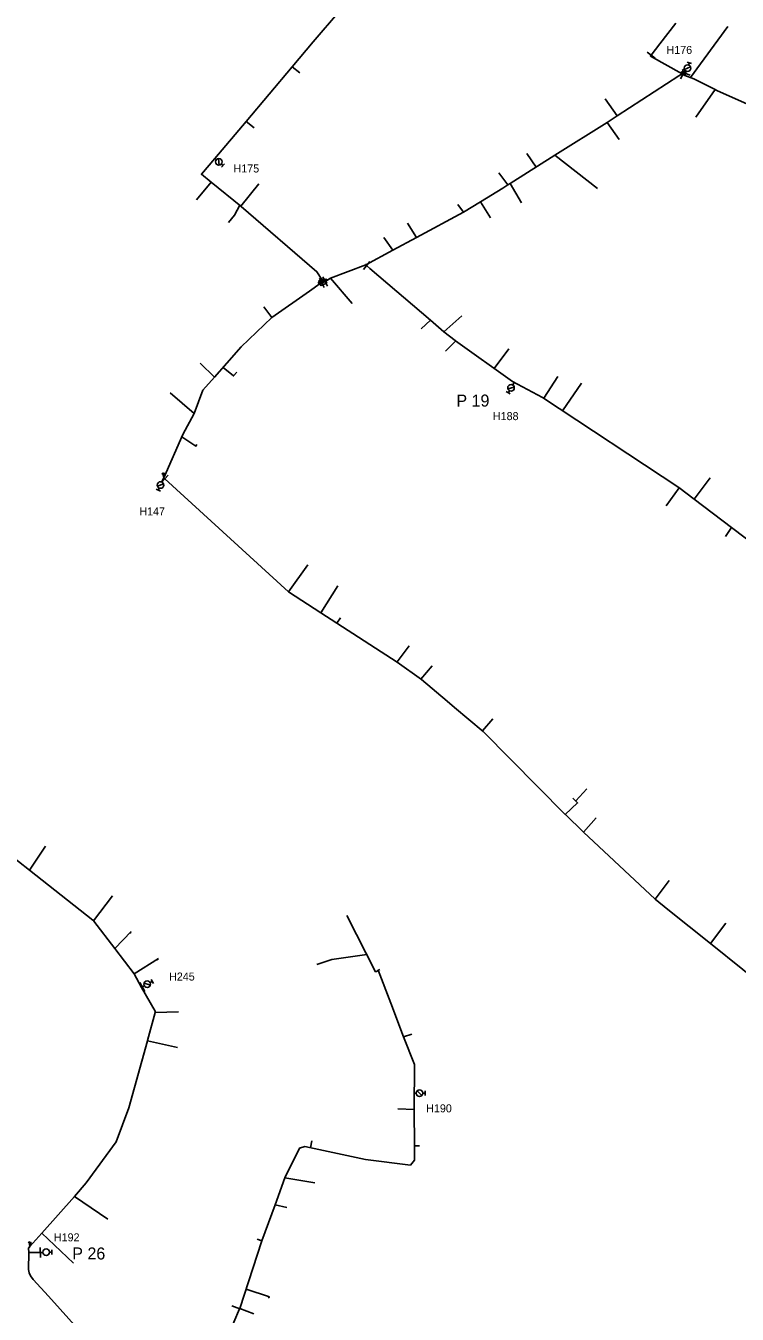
# Model space of a CAD drawing. Extents: x -548873 to -538270, y -1201997 to -1192514.
# Drawn here: x -544882.1 to -544704.3, y -1193277.9 to -1192955.8 of the extents above; entities that cross this region are included whole.
import ezdxf

# ---------------------------------------------------------------- set-up
doc = ezdxf.new("R2010")
doc.units = 0
for name, color, linetype in [('KN_HRAN_STÁTNÍ', 7, 'Continuous'), ('KN_PARC_Č', 7, 'Continuous'), ('KN_VKP_HRAN_SPORNÁ', 7, 'Continuous'), ('PK_PARC_Čv', 7, 'Continuous'), ('Vrstva 29', 7, 'Continuous'), ('Vrstva 39', 7, 'Continuous')]:
    doc.layers.add(name, color=color, linetype=linetype)

# ---------------------------------------------------------------- blocks, each defined once
blk = doc.blocks.new('160')
at = {"layer": 'KN_HRAN_STÁTNÍ'}
blk.add_circle((0, 0), 0.0458, dxfattribs=at)
blk = doc.blocks.new('147')
at = {"layer": 'KN_HRAN_STÁTNÍ'}
blk.add_line((0, 1.27), (0, -1.27), dxfattribs=at)
blk = doc.blocks.new('133')
at = {"layer": 'KN_HRAN_STÁTNÍ'}
for p, q in [((0.28, 0), (0, 0)), ((0.54, 0.58), (1.7, -0.58)), ((1.94, 0), (2.52, 0)), ((2.52, 0.58), (2.52, -0.58))]:
    blk.add_line(p, q, dxfattribs=at)
blk.add_circle((1.11, 0), 0.825, dxfattribs=at)
blk = doc.blocks.new('132')
at = {"layer": 'KN_HRAN_STÁTNÍ'}
for p, q in [((0.3, 0), (0, 0)), ((1.96, 0), (2.52, 0)), ((2.52, 0.58), (2.52, -0.58))]:
    blk.add_line(p, q, dxfattribs=at)
blk.add_circle((1.13, 0.01), 0.825, dxfattribs=at)
blk = doc.blocks.new('150')
at = {"layer": 'KN_HRAN_STÁTNÍ'}
blk.add_line((0, 1.27), (0, -1.27), dxfattribs=at)
blk = doc.blocks.new('124')
at = {"layer": 'KN_HRAN_STÁTNÍ'}
for q in [(-0.19, 1.22), (-0.19, 0.92), (0.19, 1.22), (0, 0), (0.19, 0.92)]:
    blk.add_line((0, 1.07), q, dxfattribs=at)
blk = doc.blocks.new('128')
at = {"layer": 'KN_HRAN_STÁTNÍ'}
for p, q in [((-0.19, 1.06), (-0.43, 1.15)), ((-0.36, 0.84), (-0.19, 1.06)), ((-0.19, 1.06), (-0.02, 1.25)), ((-0.19, 1.06), (0, 0)), ((0.05, 0.95), (-0.19, 1.06)), ((-0.1, 1), (0.41, 0.91)), ((-0.07, 0.82), (0.17, 0.96)), ((0.17, 0.96), (-0.02, 1.13)), ((0.17, 0.96), (0, 0)), ((0.19, 1.21), (0.17, 0.96)), ((0.17, 0.96), (0.38, 1.08)), ((0.36, 0.77), (0.17, 0.96))]:
    blk.add_line(p, q, dxfattribs=at)

msp = doc.modelspace()

# ---------------------------------------------------------------- linework, layer by layer
at = {"layer": 'KN_PARC_Č'}
for points in [[(-544715.977, -1192968.73), (-544706.675, -1192955.948)], [(-544815.524, -1192966.031), (-544813.666, -1192967.521)], [(-544709.815, -1192971.736), (-544714.672, -1192978.653)], [(-544734.327, -1192978.319), (-544737.3, -1192974.039)], [(-544827.076, -1192979.714), (-544825.064, -1192981.304)], [(-544736.804, -1192979.936), (-544733.83, -1192984.2)], [(-544754.582, -1192991.132), (-544756.863, -1192987.735)], [(-544749.883, -1192988.173), (-544739.267, -1192996.494)], [(-544835.787, -1192994.875), (-544839.498, -1192999.264)], [(-544828.339, -1193000.888), (-544823.845, -1192995.334)], [(-544761.632, -1192995.567), (-544763.921, -1192992.544)], [(-544761.043, -1192995.2), (-544758.245, -1193000.022)], [(-544828.659, -1193000.628), (-544829.984, -1193003.113), (-544831.472, -1193004.962)], [(-544772.688, -1193002.403), (-544774.146, -1193000.435)], [(-544768.504, -1192999.816), (-544765.947, -1193003.799)], [(-544784.434, -1193008.704), (-544786.713, -1193005.17)], [(-544790.421, -1193011.916), (-544792.63, -1193008.681)], [(-544805.933, -1193018.918), (-544800.548, -1193025.221)], [(-544820.638, -1193028.746), (-544822.596, -1193026.059)], [(-544781.015, -1193029.399), (-544783.309, -1193031.568)], [(-544777.608, -1193032.322), (-544773.131, -1193028.272)], [(-544774.697, -1193034.59), (-544777.212, -1193037.151)], [(-544765.084, -1193041.464), (-544761.393, -1193036.573)], [(-544834.956, -1193043.653), (-544838.538, -1193040.091)], [(-544832.822, -1193041.24), (-544830.206, -1193043.306), (-544829.378, -1193042.377)], [(-544752.679, -1193048.894), (-544749.153, -1193043.462)], [(-544747.962, -1193052.016), (-544743.241, -1193045.089)], [(-544840.067, -1193052.69), (-544846.008, -1193047.572)], [(-544843.116, -1193058.544), (-544839.602, -1193060.86), (-544839.336, -1193060.434)], [(-544715.119, -1193074.121), (-544711.117, -1193068.82)], [(-544718.863, -1193071.285), (-544722.077, -1193075.801)], [(-544705.725, -1193081.237), (-544707.291, -1193083.452)], [(-544816.431, -1193097.32), (-544811.594, -1193090.514)], [(-544808.369, -1193102.521), (-544804.17, -1193095.822)], [(-544804.394, -1193105.086), (-544803.462, -1193103.825)], [(-544789.343, -1193114.829), (-544786.345, -1193110.809)], [(-544783.393, -1193119.138), (-544780.526, -1193115.784)], [(-544767.99, -1193132.08), (-544765.369, -1193129.02)], [(-544744.693, -1193149.57), (-544741.894, -1193146.575)], [(-544747.279, -1193152.932), (-544744.236, -1193150.054), (-544745.369, -1193148.854)], [(-544742.767, -1193157.412), (-544739.553, -1193153.791)], [(-544881.16, -1193166.867), (-544877.206, -1193160.855)], [(-544724.83, -1193174.13), (-544721.34, -1193169.456)], [(-544865.223, -1193179.511), (-544860.472, -1193173.268)], [(-544794.041, -1193192.045), (-544794.713, -1193192.27), (-544801.927, -1193178.173)], [(-544859.854, -1193186.481), (-544855.791, -1193182.237)], [(-544855.998, -1193182.454), (-544855.778, -1193182.657)], [(-544711.014, -1193185.218), (-544707.143, -1193180.085)], [(-544796.901, -1193187.994), (-544805.598, -1193189.206), (-544809.4, -1193190.445)], [(-544855.029, -1193192.807), (-544848.995, -1193188.97)], [(-544849.248, -1193189.131), (-544849.087, -1193189.384)], [(-544794.096, -1193191.903), (-544793.614, -1193191.701)], [(-544849.817, -1193202.414), (-544843.924, -1193202.312)], [(-544787.702, -1193208.495), (-544785.607, -1193207.865)], [(-544851.714, -1193209.535), (-544844.202, -1193211.17)], [(-544785.084, -1193226.677), (-544789.182, -1193226.546)], [(-544810.987, -1193236.265), (-544810.622, -1193234.54)], [(-544784.953, -1193235.765), (-544783.747, -1193235.766)], [(-544817.402, -1193243.81), (-544809.85, -1193245)], [(-544869.975, -1193248.421), (-544861.582, -1193254.088)], [(-544819.838, -1193250.526), (-544816.859, -1193251.166)], [(-544878.076, -1193257.632), (-544870.187, -1193265.132)], [(-544823.113, -1193259.542), (-544824.255, -1193259.078)], [(-544827.069, -1193271.596), (-544821.192, -1193273.549)], [(-544828.595, -1193276.495), (-544830.608, -1193275.816)], [(-544821.477, -1193273.454), (-544821.308, -1193273.826)], [(-544828.668, -1193276.468), (-544825.098, -1193277.806)]]:
    msp.add_lwpolyline(points, dxfattribs=at)
at = {"layer": 'KN_VKP_HRAN_SPORNÁ'}
for points in [[(-544803.761, -1192952.099), (-544810.284, -1192959.825), (-544815.524, -1192966.031), (-544827.076, -1192979.714), (-544834.897, -1192988.977), (-544838.219, -1192992.912), (-544835.787, -1192994.875), (-544828.387, -1193000.847), (-544828.339, -1193000.888), (-544828.254, -1193000.962), (-544809.365, -1193017.288), (-544808.133, -1193019.23), (-544807.968, -1193019.616)], [(-544725.84, -1192963.12), (-544723.689, -1192960.321), (-544719.7, -1192955.161)], [(-544718.05, -1192967.82), (-544726.023, -1192963.357), (-544725.84, -1192963.12)], [(-544797.168, -1193015.535), (-544790.421, -1193011.916), (-544784.434, -1193008.704), (-544772.688, -1193002.403), (-544768.504, -1192999.816), (-544762.933, -1192996.371), (-544761.63, -1192995.566), (-544761.044, -1192995.2), (-544749.88, -1192988.171), (-544736.805, -1192979.937), (-544734.327, -1192978.319), (-544718.95, -1192968.28), (-544718.05, -1192967.82)], [(-544717.876, -1192967.919), (-544718.05, -1192967.82)], [(-544700.25, -1192976.03), (-544709.386, -1192971.951), (-544709.815, -1192971.736), (-544715.02, -1192969.11), (-544715.19, -1192969.03), (-544717.42, -1192968.18), (-544717.876, -1192967.919)], [(-544807.315, -1193019.719), (-544807.131, -1193019.641), (-544805.933, -1193018.918), (-544797.168, -1193015.535)], [(-544797.168, -1193015.535), (-544796.94, -1193015.73)], [(-544796.94, -1193015.73), (-544796.103, -1193016.449), (-544781.015, -1193029.399), (-544777.609, -1193032.322), (-544774.838, -1193034.489), (-544774.701, -1193034.587), (-544760.516, -1193044.73), (-544752.945, -1193048.718), (-544718.95, -1193071.219), (-544715.119, -1193074.121), (-544705.725, -1193081.237), (-544695.839, -1193088.726)], [(-544808.158, -1193020.078), (-544808.572, -1193020.255), (-544811.253, -1193022.14), (-544820.619, -1193028.728), (-544828.261, -1193036.084), (-544831.868, -1193040.162), (-544834.956, -1193043.653), (-544837.894, -1193046.901), (-544840.067, -1193052.69), (-544842.869, -1193057.986), (-544847.654, -1193068.79)], [(-544807.831, -1193019.939), (-544808.158, -1193020.078)], [(-544807.968, -1193019.616), (-544807.831, -1193019.939)], [(-544807.831, -1193019.939), (-544807.315, -1193019.719)], [(-544847.654, -1193068.79), (-544847.38, -1193069.04)], [(-544847.38, -1193069.04), (-544835.819, -1193079.605), (-544816.432, -1193097.319), (-544808.369, -1193102.521), (-544804.394, -1193105.086), (-544789.301, -1193114.856), (-544783.267, -1193119.229), (-544776.827, -1193124.647), (-544775.017, -1193126.169), (-544767.8, -1193132.24), (-544747.28, -1193152.931), (-544747.243, -1193152.968)], [(-544747.243, -1193152.968), (-544742.767, -1193157.412), (-544724.83, -1193174.13), (-544721.659, -1193176.674), (-544711.014, -1193185.218), (-544702.912, -1193191.719), (-544697.238, -1193196.274), (-544686.354, -1193205.008), (-544678.333, -1193211.727)], [(-544881.11, -1193260.99), (-544878.076, -1193257.632), (-544869.975, -1193248.421), (-544867.019, -1193245.046), (-544859.515, -1193234.824), (-544856.401, -1193226.265), (-544851.714, -1193209.535), (-544851.702, -1193209.494), (-544849.817, -1193202.414), (-544849.8, -1193202.142), (-544853.214, -1193196.164), (-544855.03, -1193192.807), (-544859.852, -1193186.483), (-544865.085, -1193179.621), (-544865.348, -1193179.412), (-544881.16, -1193166.867), (-544886.663, -1193162.532), (-544887.958, -1193163.66), (-544893.185, -1193167.984), (-544902.737, -1193183.81), (-544909.795, -1193194.916), (-544913.024, -1193200.427), (-544920.746, -1193213.299), (-544926.86, -1193222.93)], [(-544842.37, -1193306.78), (-544842.26, -1193306.65), (-544836.075, -1193293.565), (-544834.587, -1193290.133), (-544831.585, -1193283.21), (-544828.691, -1193276.537), (-544828.668, -1193276.468), (-544823.113, -1193259.542), (-544819.838, -1193250.526), (-544817.387, -1193243.768), (-544813.71, -1193236.351), (-544812.402, -1193235.968), (-544797.18, -1193239.166), (-544785.987, -1193240.585), (-544785.011, -1193239.406), (-544784.953, -1193235.765), (-544785.084, -1193226.716), (-544784.98, -1193215.478), (-544787.684, -1193208.541), (-544790.928, -1193200.123), (-544794.096, -1193191.903)], [(-544842.82, -1193306.87), (-544843.31, -1193306.48), (-544845.95, -1193306.52), (-544849.84, -1193302.54), (-544854.6, -1193297.59), (-544859.76, -1193291.71), (-544868.41, -1193282.27), (-544876.48, -1193273.39), (-544880.25, -1193269.19), (-544880.94, -1193268.31), (-544881.3, -1193267.57), (-544881.46, -1193266.67), (-544881.39, -1193262.45), (-544881.42, -1193261.36), (-544881.11, -1193260.99)]]:
    msp.add_lwpolyline(points, dxfattribs=at)
at = {"layer": 'PK_PARC_Čv'}
for points in [[(-544717.42, -1192968.18), (-544717.25, -1192967.72), (-544717.14, -1192967.43)], [(-544834.897, -1192988.977), (-544834.74, -1192989.11)], [(-544807.434, -1193018.933), (-544806.924, -1193020.129), (-544808.365, -1193020.743), (-544808.875, -1193019.547), (-544807.434, -1193018.933)], [(-544760.079, -1193044.96), (-544760.3, -1193045.34)], [(-544847.654, -1193068.79), (-544848, -1193069.57)], [(-544853.214, -1193196.164), (-544852.75, -1193195.922)], [(-544785.046, -1193222.627), (-544784.84, -1193222.63)], [(-544881.39, -1193262.45), (-544878.5, -1193262.45), (-544878.14, -1193262.44)]]:
    msp.add_lwpolyline(points, dxfattribs=at)

# ---------------------------------------------------------------- block references
for name, p, xscale, yscale, rotation in [('133', (-544717.14, -1192967.43), 0.9999999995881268, 0.9999999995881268, 69.99999934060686), ('150', (-544717.25, -1192967.72), 0.9999999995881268, 0.9999999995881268, 69.99999934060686), ('133', (-544834.74, -1192989.11), 1.0000000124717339, 1.0000000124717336, -40.00000131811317), ('133', (-544760.3, -1193045.34), 0.9999999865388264, 0.9999999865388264, -120.00000044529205), ('133', (-544848, -1193069.57), 1.0000000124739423, 1.000000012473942, -112.99999954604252), ('150', (-544853.017, -1193196.062), 1.0072562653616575, 1.0072562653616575, 28.76666512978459), ('133', (-544852.75, -1193195.922), 1.0072562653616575, 1.0072562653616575, 28.76666512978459), ('150', (-544878.5, -1193262.45), 1.000000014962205, 1.0000000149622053, 0.9999999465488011), ('132', (-544878.14, -1193262.44), 1.00000001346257, 1.0000000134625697, 1.9999999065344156)]:
    msp.add_blockref(name, p, dxfattribs=dict(at, xscale=xscale, yscale=yscale, rotation=rotation))
msp.add_blockref('133', (-544784.84, -1193222.63), dxfattribs=at)
at = {"layer": 'Vrstva 29'}
for name, p, xscale, yscale, rotation in [('147', (-544725.84, -1192963.12), 0.9999999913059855, 0.9999999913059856, 52.999998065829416), ('147', (-544717.876, -1192967.919), 1.0037042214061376, 1.0037042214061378, 150.62079160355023), ('160', (-544718.05, -1192967.82), 1.000000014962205, 1.0000000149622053, 89.0000000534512), ('147', (-544796.94, -1193015.73), 1.0000000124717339, 1.0000000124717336, 139.99999868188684), ('160', (-544797.168, -1193015.535), 1.0011217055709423, 1.0011217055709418, -96.5826098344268), ('147', (-544807.968, -1193019.616), 0.9999999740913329, 0.9999999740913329, 114.00000060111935), ('147', (-544808.158, -1193020.078), 1.019856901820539, 1.0198569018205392, -153.606016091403), ('160', (-544807.831, -1193019.939), 1.019856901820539, 1.0198569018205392, -153.606016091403), ('147', (-544807.315, -1193019.719), 1.019856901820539, 1.0198569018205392, -153.606016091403), ('147', (-544847.38, -1193069.04), 1.0000000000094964, 1.0000000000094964, 137.9999986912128), ('160', (-544847.654, -1193068.79), 1.0000000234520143, 1.0000000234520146, 101.99999938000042), ('160', (-544747.243, -1193152.968), 0.999999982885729, 0.9999999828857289, 135), ('160', (-544794.096, -1193191.903), 1.0000000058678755, 1.0000000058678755, -68.00000099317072), ('160', (-544881.11, -1193260.99), 1.0000000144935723, 1.0000000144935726, 139.00000089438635)]:
    msp.add_blockref(name, p, dxfattribs=dict(at, xscale=xscale, yscale=yscale, rotation=rotation))
at = {"layer": 'Vrstva 39'}
for name, p in [('124', (-544717.876, -1192967.919)), ('128', (-544847.654, -1193068.79)), ('128', (-544881.11, -1193260.99))]:
    msp.add_blockref(name, p, dxfattribs=at)

# ---------------------------------------------------------------- texts
at = {"layer": 'PK_PARC_Čv'}
for s, height, p in [('H176', 2, (-544721.98, -1192962.83)), ('H175', 2, (-544830.2, -1192992.46)), ('P 19', 3, (-544774.5, -1193050.99)), ('H188', 2, (-544765.37, -1193054.37)), ('H147', 2, (-544853.74, -1193078.19)), ('H245', 2, (-544846.3, -1193194.462)), ('H190', 2, (-544782.04, -1193227.41)), ('H192', 2, (-544875.09, -1193259.66)), ('P 26', 3, (-544870.51, -1193264.19))]:
    msp.add_text(s, height=height, dxfattribs=at).set_placement(p)

doc.saveas('drawing.dxf')
